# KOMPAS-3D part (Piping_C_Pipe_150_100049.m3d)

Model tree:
1. Plane XY
2. Plane ZX
3. Plane ZY
4. X Axis
5. Y Axis
6. Z Axis
7. Origin
8. Path  (labels: Отвод 90 Dy 150; Труба Dy 150; Задвижка Dy 150)
9. Plane of section
10. Section of pipe
11. Pipe
     Толщина стенки 1 = 1

Referenced files in C:\Program Files\ASCON\KOMPAS-3D V10\Libs\Piping\Models\Tanks\: Tanks.a3d
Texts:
  Pipe Dn 150
  Steel ASTM A295
  Three Point Plane
  Plane at Angle
  Line and Point Plane
  Axis through Two Vertices
  Axis of Feature
  Axis of Conical Surface
  Axis through Edge
  Приклеить элемент выдавливания
  Приклеить элемент вращения
  Приклеить кинематический элемент
  Приклеить элемент по сечениям
  Trim by Surface
  Trim by Sketch
  Feature with No History
  Intersection Axis of Two Planes
  Two Line Plane
  Line and Face Plane
  Bend by line
  Hole in sheet body
  Cut in sheet body
  Point in CM
  Linear Dimension from Line to Point
  Surface Finish Symbol
  Geometric Tolerance Symbol
  Текст на чертеже
  Линия-выноска #1
  Линия-выноска #2
  Линия-выноска #3
  Отклонения формы и база
  Марка координационной оси
  Марка/позиционное обозначение с линией-выноской
  Марка/позиционное обозначение на линии
  Марка/позиционное обозначение без линии-выноски
  Отвод 90 Dy 150
  Труба Dy 150
  Задвижка Dy 150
